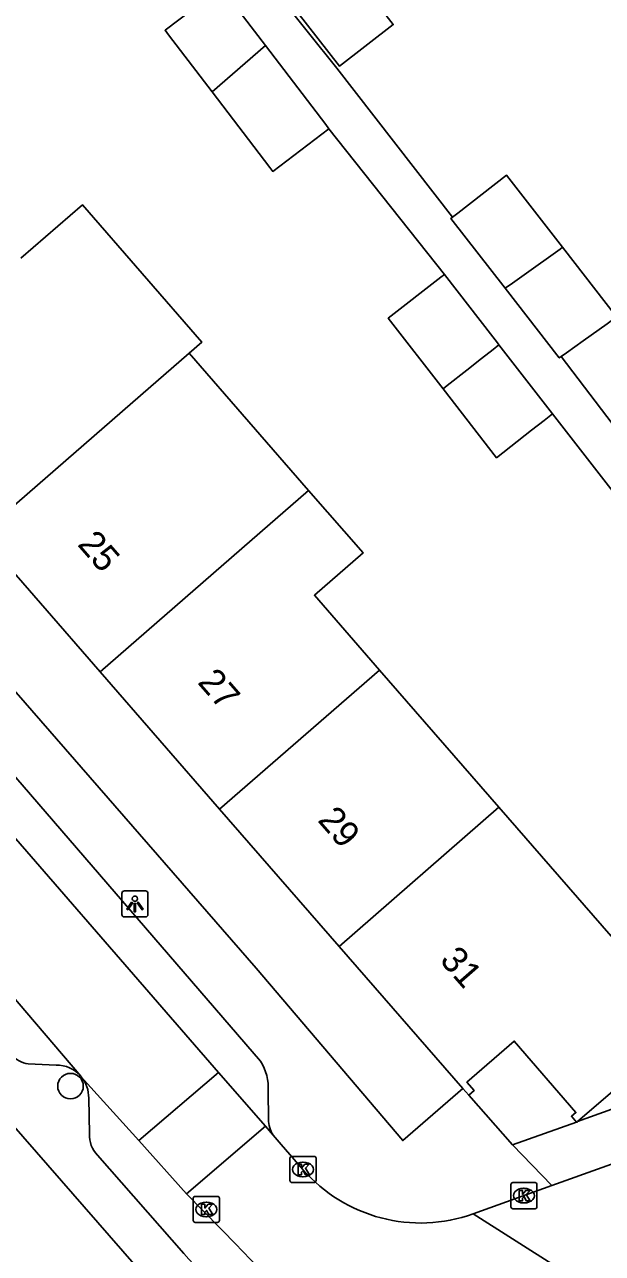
# Model space of a CAD drawing. Extents: x 162532 to 163264, y 381233 to 382042.
# Drawn here: x 162678.19 to 162700.32, y 381767.09 to 381814.16 of the extents above; entities that cross this region are included whole.
import ezdxf

# ---------------------------------------------------------------- set-up
doc = ezdxf.new("R2010")
doc.units = 0
for name, color, linetype in [('IMGEO_Boom', 7, 'Continuous'), ('IMGEO_Kolk', 7, 'Continuous'), ('IMGEO_Lichtpunt', 7, 'Continuous'), ('IMGEO_Pand', 7, 'Continuous'), ('IMGEO_Pand_nummerreeks', 7, 'Continuous'), ('IMGEO_Rijbaan_lokaal_open', 7, 'Continuous'), ('IMGEO_Voetpad_open', 7, 'Continuous')]:
    doc.layers.add(name, color=color, linetype=linetype)

msp = doc.modelspace()

# ---------------------------------------------------------------- linework, layer by layer
at = {"layer": 'IMGEO_Boom'}
msp.add_circle((162679.951, 381773.503), 0.489, dxfattribs=at)
at = {"layer": 'IMGEO_Kolk'}
for p, q in [((162688.353, 381769.885), (162688.353, 381770.737)), ((162688.428, 381770.811), (162689.28, 381770.811)), ((162688.841, 381770.591), (162688.866, 381770.591)), ((162689.354, 381770.737), (162689.354, 381769.885)), ((162688.864, 381770.031), (162688.839, 381770.031)), ((162689.28, 381769.811), (162688.428, 381769.811)), ((162696.813, 381768.882), (162696.813, 381769.734)), ((162696.888, 381769.808), (162697.74, 381769.808)), ((162697.301, 381769.588), (162697.326, 381769.588)), ((162697.814, 381769.734), (162697.814, 381768.882)), ((162684.652, 381768.355), (162684.652, 381769.207)), ((162684.727, 381769.281), (162685.579, 381769.281)), ((162685.14, 381769.061), (162685.165, 381769.061)), ((162685.653, 381769.207), (162685.653, 381768.355)), ((162697.74, 381768.808), (162696.888, 381768.808)), ((162697.324, 381769.028), (162697.299, 381769.028)), ((162685.579, 381768.281), (162684.727, 381768.281)), ((162685.163, 381768.501), (162685.138, 381768.501))]:
    msp.add_line(p, q, dxfattribs=at)
for points in [[(162688.353, 381769.885), (162688.353, 381770.737)], [(162688.428, 381770.811), (162689.28, 381770.811)], [(162688.674, 381770.511), (162688.797, 381770.511), (162688.797, 381770.36), (162688.927, 381770.511), (162689.091, 381770.511), (162688.945, 381770.36), (162689.098, 381770.111), (162688.946, 381770.111), (162688.861, 381770.275), (162688.797, 381770.208), (162688.797, 381770.111), (162688.674, 381770.111), (162688.674, 381770.511)], [(162689.354, 381770.737), (162689.354, 381769.885)], [(162689.28, 381769.811), (162688.428, 381769.811)], [(162696.813, 381768.882), (162696.813, 381769.734)], [(162696.888, 381769.808), (162697.74, 381769.808)], [(162697.814, 381769.734), (162697.814, 381768.882)], [(162684.652, 381768.355), (162684.652, 381769.207)], [(162684.727, 381769.281), (162685.579, 381769.281)], [(162685.653, 381769.207), (162685.653, 381768.355)], [(162697.134, 381769.508), (162697.257, 381769.508), (162697.257, 381769.357), (162697.387, 381769.508), (162697.551, 381769.508), (162697.405, 381769.357), (162697.558, 381769.108), (162697.406, 381769.108), (162697.321, 381769.272), (162697.257, 381769.205), (162697.257, 381769.108), (162697.134, 381769.108), (162697.134, 381769.508)], [(162684.973, 381768.981), (162685.096, 381768.981), (162685.096, 381768.83), (162685.226, 381768.981), (162685.39, 381768.981), (162685.244, 381768.83), (162685.397, 381768.581), (162685.245, 381768.581), (162685.16, 381768.745), (162685.096, 381768.678), (162685.096, 381768.581), (162684.973, 381768.581), (162684.973, 381768.981)], [(162697.74, 381768.808), (162696.888, 381768.808)], [(162685.579, 381768.281), (162684.727, 381768.281)]]:
    msp.add_lwpolyline(points, dxfattribs=at)
for centre, start, end in [((162688.43, 381770.735), 91.552, 178.448), ((162688.43, 381770.735), 91.552, 178.448), ((162689.278, 381770.735), 1.552, 88.448), ((162689.278, 381770.735), 1.552, 88.448), ((162688.43, 381769.887), 181.552, 268.448), ((162688.43, 381769.887), 181.552, 268.448), ((162689.278, 381769.887), 271.552, 358.448), ((162689.278, 381769.887), 271.552, 358.448), ((162696.89, 381769.732), 91.552, 178.448), ((162696.89, 381769.732), 91.552, 178.448), ((162697.738, 381769.732), 1.552, 88.448), ((162697.738, 381769.732), 1.552, 88.448), ((162684.729, 381769.205), 91.552, 178.448), ((162684.729, 381769.205), 91.552, 178.448), ((162685.577, 381769.205), 1.552, 88.448), ((162685.577, 381769.205), 1.552, 88.448), ((162696.89, 381768.884), 181.552, 268.448), ((162696.89, 381768.884), 181.552, 268.448), ((162697.738, 381768.884), 271.552, 358.448), ((162697.738, 381768.884), 271.552, 358.448), ((162684.729, 381768.357), 181.552, 268.448), ((162684.729, 381768.357), 181.552, 268.448), ((162685.577, 381768.357), 271.552, 358.448), ((162685.577, 381768.357), 271.552, 358.448)]:
    msp.add_arc(centre, 0.0765, start, end, dxfattribs=at)
for centre, major_axis, ratio, start_param, end_param in [((162688.84, 381770.311), (-0.387, 0.002), 0.722429, 4.712389, 7.853982), ((162688.865, 381770.311), (-0.39, 0.002), 0.717154, 1.570796, 4.712389), ((162697.3, 381769.308), (-0.387, 0.002), 0.722429, 4.712389, 7.853982), ((162697.325, 381769.308), (-0.39, 0.002), 0.717154, 1.570796, 4.712389), ((162685.139, 381768.781), (-0.387, 0.002), 0.722429, 4.712389, 7.853982), ((162685.164, 381768.781), (-0.39, 0.002), 0.717154, 1.570796, 4.712389)]:
    msp.add_ellipse(centre, major_axis=major_axis, ratio=ratio, start_param=start_param, end_param=end_param, dxfattribs=at)
at = {"layer": 'IMGEO_Lichtpunt'}
for p, q in [((162681.919, 381780.884), (162681.919, 381780.077)), ((162681.919, 381780.884), (162681.919, 381780.077)), ((162682.821, 381780.979), (162682.013, 381780.979)), ((162682.821, 381780.979), (162682.013, 381780.979)), ((162682.915, 381780.077), (162682.915, 381780.884)), ((162682.915, 381780.077), (162682.915, 381780.884)), ((162682.013, 381779.983), (162682.821, 381779.983)), ((162682.013, 381779.983), (162682.821, 381779.983))]:
    msp.add_line(p, q, dxfattribs=at)
for points in [[(162682.293, 381780.548), (162682.332, 381780.52), (162682.144, 381780.258), (162682.106, 381780.285), (162682.293, 381780.548)], [(162682.395, 381780.5), (162682.442, 381780.5), (162682.442, 381780.178), (162682.395, 381780.178), (162682.395, 381780.5)], [(162682.505, 381780.52), (162682.543, 381780.547), (162682.73, 381780.285), (162682.691, 381780.257), (162682.505, 381780.52)]]:
    msp.add_lwpolyline(points, dxfattribs=at)
msp.add_circle((162682.418, 381780.682), 0.0994, dxfattribs=at)
for centre, start, end in [((162682.013, 381780.884), 90, 180), ((162682.013, 381780.884), 90, 180), ((162682.821, 381780.884), 0, 90), ((162682.821, 381780.884), 0, 90), ((162682.013, 381780.077), 180, 270), ((162682.013, 381780.077), 180, 270), ((162682.821, 381780.077), 270, 0), ((162682.821, 381780.077), 270, 360)]:
    msp.add_arc(centre, 0.0946, start, end, dxfattribs=at)
at = {"layer": 'IMGEO_Pand'}
for points in [[(162688.211, 381815.198), (162690.254, 381812.565), (162692.309, 381814.16), (162690.328, 381816.713)], [(162685.615, 381815.497), (162683.576, 381813.944), (162683.709, 381813.768), (162685.374, 381811.583)], [(162687.415, 381813.36), (162685.857, 381815.405), (162685.724, 381815.58), (162685.615, 381815.497)], [(162685.374, 381811.583), (162687.415, 381813.36)], [(162689.845, 381810.17), (162689.726, 381810.327), (162687.415, 381813.36)], [(162685.374, 381811.583), (162687.578, 381808.69), (162687.697, 381808.533), (162689.845, 381810.17)], [(162698.794, 381805.629), (162696.65, 381808.389), (162694.788, 381806.943), (162694.58, 381806.781)], [(162684.494, 381801.576), (162684.981, 381802), (162680.405, 381807.258), (162678.052, 381805.21)], [(162694.58, 381806.781), (162694.519, 381806.734), (162696.598, 381804.058)], [(162698.794, 381805.629), (162698.698, 381805.56), (162697.323, 381804.577), (162696.875, 381804.256), (162696.598, 381804.058)], [(162698.736, 381801.444), (162698.944, 381801.592), (162699.581, 381802.048), (162700.497, 381802.703), (162700.862, 381802.965), (162698.794, 381805.629)], [(162694.271, 381804.584), (162694.138, 381804.481), (162692.118, 381802.913), (162694.218, 381800.21)], [(162696.36, 381801.894), (162696.298, 381801.974), (162696.119, 381802.205), (162694.271, 381804.584)], [(162696.598, 381804.058), (162698.667, 381801.394), (162698.736, 381801.444)], [(162676.507, 381794.626), (162682.629, 381799.953), (162684.494, 381801.576)], [(162689.069, 381796.318), (162684.494, 381801.576)], [(162694.218, 381800.21), (162694.375, 381800.334), (162695.128, 381800.925), (162695.693, 381801.37), (162696.131, 381801.714), (162696.36, 381801.894)], [(162698.409, 381799.256), (162696.36, 381801.894)], [(162698.409, 381799.256), (162698.085, 381799.001), (162697.61, 381798.628), (162696.267, 381797.571), (162694.218, 381800.21)], [(162681.084, 381789.369), (162687.206, 381794.697), (162689.069, 381796.318)], [(162691.782, 381789.44), (162689.291, 381792.301), (162691.154, 381793.922), (162689.069, 381796.318)], [(162676.507, 381794.626), (162681.084, 381789.369)], [(162681.084, 381789.369), (162685.66, 381784.112)], [(162685.66, 381784.112), (162691.782, 381789.44)], [(162696.359, 381784.183), (162691.782, 381789.44)], [(162690.237, 381778.855), (162696.359, 381784.183)], [(162696.359, 381784.183), (162700.653, 381779.252), (162703.745, 381781.827), (162706.667, 381778.414), (162699.372, 381772.144)], [(162685.66, 381784.112), (162690.237, 381778.855)], [(162694.979, 381773.409), (162690.237, 381778.855)], [(162699.326, 381772.127), (162699.131, 381772.351), (162699.306, 381772.491), (162696.945, 381775.228), (162695.132, 381773.65), (162695.409, 381773.331), (162695.203, 381773.152)], [(162695.203, 381773.152), (162694.979, 381773.409)], [(162699.372, 381772.144), (162699.337, 381772.114), (162699.326, 381772.127)]]:
    msp.add_lwpolyline(points, dxfattribs=at)
at = {"layer": 'IMGEO_Rijbaan_lokaal_open'}
for points in [[(162680.341, 381773.889), (162662.382, 381794.94)], [(162675.182, 381786.047), (162685.624, 381774.027)], [(162736.996, 381783.467), (162733.281, 381782.136), (162727.293, 381779.975), (162723.508, 381778.659), (162709.271, 381773.592), (162698.385, 381769.691)], [(162680.363, 381773.863), (162680.341, 381773.889)], [(162682.563, 381771.414), (162680.363, 381773.863)], [(162685.624, 381774.027), (162682.563, 381771.414)], [(162687.414, 381771.967), (162685.624, 381774.027)], [(162684.387, 381769.383), (162687.414, 381771.967)], [(162687.717, 381771.618), (162687.414, 381771.967)], [(162682.563, 381771.414), (162684.387, 381769.383)], [(162687.717, 381771.618), (162688.021, 381771.269), (162688.851, 381770.313)], [(162695.37, 381768.61), (162698.385, 381769.691)], [(162686.333, 381767.393), (162684.387, 381769.383)], [(162695.37, 381768.61), (162703.464, 381763.466)]]:
    msp.add_lwpolyline(points, dxfattribs=at)
for centre, radius, start, end in [((162693.356, 381774.23), 5.97, 221.0047, 289.7142), ((162700.642, 381780.747), 19.573, 223.0226, 242.7418)]:
    msp.add_arc(centre, radius, start, end, dxfattribs=at)
at = {"layer": 'IMGEO_Voetpad_open'}
for points in [[(162694.979, 381773.409), (162692.677, 381771.414), (162687.062, 381778.024), (162646.757, 381824.316)], [(162694.58, 381806.781), (162690.152, 381812.486), (162681.469, 381823.324)], [(162641.055, 381814.077), (162691.781, 381755.909), (162689.516, 381753.943)], [(162694.271, 381804.584), (162689.845, 381810.17)], [(162703.136, 381795.671), (162698.736, 381801.444)], [(162703.003, 381793.336), (162698.409, 381799.256)], [(162675.808, 381785.84), (162677.178, 381785.697), (162677.863, 381785.328), (162687.231, 381774.456)], [(162713.049, 381777.067), (162699.372, 381772.144)], [(162679.399, 381774.307), (162678.333, 381774.357)], [(162687.525, 381773.31), (162687.534, 381772.229)], [(162680.65, 381773.042), (162680.674, 381771.674)], [(162696.883, 381771.248), (162695.203, 381773.152)], [(162699.326, 381772.127), (162696.883, 381771.248)], [(162698.385, 381769.691), (162696.883, 381771.248)], [(162680.99, 381770.86), (162684.295, 381767.095)]]:
    msp.add_lwpolyline(points, dxfattribs=at)
for centre, radius, start, end in [((162678.443, 381775.294), 0.943, 217.9257, 263.3073), ((162679.42, 381773.083), 1.224, 41.1812, 90.9616), ((162685.506, 381773.403), 2.021, 357.3675, 31.4097), ((162679.362, 381773.053), 1.288, 359.5322, 39.0044), ((162688.706, 381772.247), 1.172, 180.8814, 212.4655), ((162681.756, 381771.626), 1.083, 177.4331, 225), ((162698.833, 381779.886), 19.364, 221.3423, 234.9123)]:
    msp.add_arc(centre, radius, start, end, dxfattribs=at)

# ---------------------------------------------------------------- texts
at = {"layer": 'IMGEO_Pand_nummerreeks'}
for s, rotation, p in [('25', 311.0465, (162680.187, 381794.236)), ('27', 311.0448, (162684.785, 381788.953)), ('29', 311.0448, (162689.384, 381783.671)), ('31', 311.0448, (162694.058, 381778.304))]:
    msp.add_text(s, height=1, rotation=rotation, dxfattribs=at).set_placement(p)

doc.saveas('drawing.dxf')
